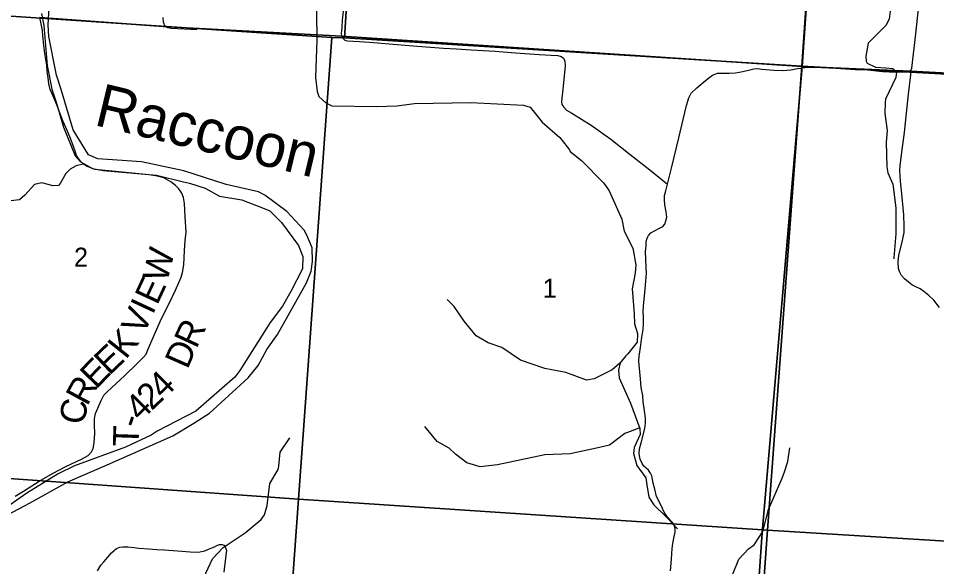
# Model space of a CAD drawing. Extents: x 1878108 to 2183446, y 146837 to 508383.
# Drawn here: x 2005354 to 2016069, y 304666 to 311060 of the extents above; entities that cross this region are included whole.
import ezdxf

# ---------------------------------------------------------------- set-up
doc = ezdxf.new("R2010")
doc.units = 0
for name, color, linetype in [('GM_X_Major_River', 7, 'Continuous'), ('GM_X_Major_River_Text', 7, 'Continuous'), ('GM_X_Minor_River', 7, 'Continuous'), ('GM_X_Section', 7, 'Continuous'), ('GM_X_Section_Text', 7, 'Continuous'), ('GM_X_Township', 7, 'Continuous'), ('GM_X_Township_Road', 7, 'Continuous'), ('GM_X_Township_Road_Text', 7, 'Continuous')]:
    doc.layers.add(name, color=color, linetype=linetype)

msp = doc.modelspace()

# ---------------------------------------------------------------- linework, layer by layer
at = {"layer": 'GM_X_Major_River'}
for points in [[(2005228, 305270), (2005424, 305377), (2005486, 305406), (2005933, 305654), (2006389, 305852), (2007158, 306191), (2007403, 306340), (2007585, 306455), (2008036, 306866), (2008152, 307010), (2008253, 307199), (2008377, 307372), (2008717, 307976), (2008771, 308113), (2008788, 308223), (2008782, 308383), (2008721, 308531), (2008687, 308589), (2008487, 308809), (2008230, 308998), (2008156, 309038), (2007778, 309121), (2007285, 309283), (2006791, 309386), (2006283, 309420), (2006174, 309468), (2005992, 309760), (2005852, 310230), (2005798, 310396), (2005710, 310847), (2005702, 310983), (2005715, 311185)], [(2005624, 311117), (2005650, 310977), (2005691, 310510), (2005744, 310234), (2005795, 310084), (2005879, 309791), (2006018, 309457), (2006081, 309387), (2006221, 309308), (2006343, 309284), (2006967, 309230), (2007281, 309155), (2007351, 309137), (2007534, 309078), (2007702, 308986), (2007960, 308943), (2008222, 308844), (2008288, 308816), (2008425, 308680), (2008624, 308413), (2008674, 308281), (2008670, 308140), (2008535, 307873), (2008438, 307705), (2008292, 307512), (2007940, 306953), (2007878, 306877), (2007423, 306481), (2006972, 306247), (2006904, 306200), (2006604, 306061), (2006009, 305842), (2005819, 305748), (2005452, 305524), (2005154, 305314)]]:
    msp.add_lwpolyline(points, dxfattribs=at)
at = {"layer": 'GM_X_Minor_River'}
for points in [[(2008830, 311302), (2008838, 310858), (2008838, 310810), (2008820, 310370), (2008840, 310206), (2008860, 310148), (2008940, 310073), (2009012, 310039), (2009536, 310034), (2009772, 310040), (2009978, 310067), (2010635, 310079), (2011247, 310048), (2011327, 310026), (2011467, 309849), (2011672, 309671), (2011758, 309562), (2011786, 309528), (2011794, 309506), (2011924, 309404), (2012186, 309137), (2012246, 309049), (2012394, 308718), (2012424, 308579), (2012524, 308381), (2012558, 308186), (2012550, 308090), (2012518, 307907), (2012539, 307614), (2012543, 307497), (2012579, 307385), (2012573, 307283), (2012467, 307146), (2012443, 307126), (2012375, 307044), (2012357, 306959), (2012365, 306869), (2012495, 306572), (2012607, 306277), (2012609, 306207), (2012541, 306054), (2012533, 305984), (2012569, 305845), (2012677, 305701), (2012687, 305620), (2012711, 305478), (2012767, 305388), (2012909, 305251), (2012937, 305223), (2013045, 305107)], [(2015535, 311207), (2015513, 311052), (2015477, 310978), (2015271, 310771), (2015241, 310618), (2015245, 310560), (2015259, 310536), (2015355, 310490), (2015477, 310482), (2015559, 310476), (2015599, 310434), (2015591, 310370), (2015471, 310118), (2015467, 310084), (2015464, 309952), (2015492, 309751), (2015480, 309615), (2015488, 309327), (2015500, 309259), (2015558, 309127), (2015592, 308852), (2015594, 308547), (2015568, 308268), (2015569, 308254)], [(2006124, 309363), (2006027, 309342), (2005957, 309301), (2005907, 309251), (2005843, 309133), (2005821, 309109), (2005759, 309106), (2005627, 309142), (2005541, 309122), (2005429, 308998), (2005368, 308945), (2005266, 308931), (2005092, 309003), (2005040, 308991), (2005018, 309003), (2004990, 309023), (2004894, 309098), (2004790, 309120), (2004596, 309200), (2004314, 309298), (2004220, 309346), (2004198, 309496), (2004124, 309591)], [(2012374, 307038), (2012283, 306963), (2012071, 306856), (2011985, 306842), (2011741, 306930), (2011498, 306978), (2011214, 307074), (2010994, 307223), (2010834, 307277), (2010696, 307359), (2010556, 307529), (2010440, 307698), (2010358, 307780)], [(2012604, 306285), (2012429, 306220), (2012251, 306082), (2012099, 306049), (2011794, 305983), (2011498, 305970), (2010946, 305853), (2010743, 305831), (2010587, 305877), (2010455, 305979), (2010379, 306046), (2010241, 306126), (2010095, 306300)], [(2006783, 303933), (2007000, 303932), (2007116, 303900), (2007250, 303934), (2007392, 304049), (2007470, 304145), (2007524, 304322), (2007527, 304394), (2007523, 304457), (2007543, 304589), (2007621, 304758), (2007745, 304890), (2008001, 305059), (2008189, 305214), (2008225, 305270), (2008257, 305379), (2008290, 305636), (2008384, 305799), (2008394, 305837), (2008408, 306001), (2008522, 306170)], [(2015152, 303640), (2015098, 303674), (2014911, 303777), (2014615, 303987), (2014496, 304053), (2014178, 304152), (2013904, 304166), (2013850, 304182), (2013729, 304311), (2013691, 304456), (2013687, 304570), (2013760, 304754), (2013872, 304874), (2013940, 304922), (2014039, 305077), (2014107, 305333), (2014266, 305696), (2014293, 305772), (2014331, 305892), (2014356, 306052)]]:
    msp.add_lwpolyline(points, dxfattribs=at)
at = {"layer": 'GM_X_Section'}
for points in [[(2004181, 316598), (2009499, 316192), (2009160, 310834), (2009010, 310838), (2003743, 311188)], [(2009499, 316192), (2014863, 315795), (2014496, 310501), (2009160, 310834)], [(2014863, 315795), (2020171, 315488), (2019788, 310210), (2014496, 310501)], [(2003529, 311206), (2003743, 311188), (2009010, 310838), (2008621, 305452), (2003175, 305842)], [(2009010, 310838), (2009160, 310834), (2014496, 310501), (2014095, 305091), (2008621, 305452)], [(2014496, 310501), (2019788, 310210), (2019399, 304766), (2014095, 305091)], [(2008621, 305452), (2008239, 300132), (2002740, 300503), (2003175, 305842)], [(2014095, 305091), (2013713, 299765), (2008239, 300132), (2008621, 305452)], [(2014095, 305091), (2019399, 304766), (2019035, 299380), (2013711, 299725), (2013713, 299765)]]:
    msp.add_lwpolyline(points, close=True, dxfattribs=at)
at = {"layer": 'GM_X_Township'}
for points in [[(2047300, 315672), (2046896, 308713), (2044671, 308870), (2043687, 308921), (2041417, 309015), (2041247, 309014), (2037098, 309204), (2031112, 309548), (2029101, 309655), (2027751, 309726), (2027032, 309764), (2024940, 309906), (2023383, 310046), (2023252, 310040), (2022929, 310063), (2022792, 310066), (2015762, 310446), (2014499, 310497), (2014658, 312772)], [(2014658, 312772), (2014499, 310497), (2009126, 310852), (2007464, 310941), (2007099, 310961), (2005605, 311070)], [(2005605, 311070), (2007099, 310961), (2007464, 310941), (2009126, 310852), (2014499, 310497), (2014033, 305062), (2013952, 303891), (2013758, 301109), (2013695, 300200), (2013680, 299994), (2013409, 296082), (2013072, 291229), (2012800, 287595), (2012779, 287296), (2012659, 285561), (2012605, 284781), (2012547, 283991), (2012147, 278506), (2012135, 278344), (2010382, 278455), (2009628, 278502), (2004300, 278840)], [(2012659, 285561), (2012779, 287296), (2012800, 287595), (2013072, 291229), (2013409, 296082), (2013680, 299994), (2013695, 300200), (2013758, 301109), (2013952, 303891), (2014033, 305062), (2014499, 310497), (2015762, 310446), (2022792, 310066), (2022929, 310063), (2023252, 310040), (2023383, 310046), (2024940, 309906), (2027032, 309764)]]:
    msp.add_lwpolyline(points, dxfattribs=at)
at = {"layer": 'GM_X_Township_Road'}
for points in [[(2015762, 310446), (2015780, 310481), (2015826, 310879), (2015870, 311283), (2015910, 311621), (2015935, 311858), (2015982, 312230)], [(2009150, 311210), (2009134, 311038), (2009129, 310960), (2009124, 310907)], [(2005315, 305486), (2005414, 305548), (2005596, 305661), (2005752, 305751), (2005908, 305835), (2006089, 305918), (2006170, 305964), (2006208, 306004), (2006228, 306045), (2006238, 306110), (2006246, 306221), (2006241, 306315), (2006243, 306389), (2006253, 306453), (2006280, 306516), (2006322, 306604), (2006353, 306666), (2006391, 306704), (2006597, 306895), (2006745, 307038), (2006815, 307108), (2006844, 307145), (2006865, 307196), (2006901, 307277), (2006954, 307399), (2007026, 307559), (2007112, 307734), (2007189, 307891), (2007254, 308042), (2007271, 308098), (2007283, 308184), (2007293, 308351), (2007300, 308469), (2007311, 308566), (2007300, 308745), (2007292, 308902), (2007281, 308970), (2007260, 309022), (2007227, 309070), (2007188, 309111), (2007135, 309154), (2007053, 309199), (2006979, 309220), (2006875, 309234), (2006645, 309260), (2006448, 309279), (2006248, 309298), (2006199, 309315), (2006157, 309334), (2006124, 309353), (2006089, 309384), (2006064, 309414), (2006034, 309461), (2006016, 309510), (2005969, 309640), (2005926, 309745), (2005874, 309866), (2005802, 310053), (2005761, 310151), (2005727, 310232), (2005710, 310296), (2005700, 310367), (2005690, 310442), (2005686, 310511), (2005664, 310650), (2005650, 310749), (2005640, 310855), (2005634, 310920), (2005619, 310995), (2005603, 311070)], [(2007054, 310997), (2007049, 311015), (2007045, 311070)], [(2007438, 310928), (2007137, 310941), (2007100, 310948), (2007075, 310962), (2007059, 310982), (2007054, 310997)], [(2009124, 310907), (2009122, 310891), (2009126, 310852), (2009139, 310827), (2009163, 310806), (2009194, 310797), (2009334, 310790), (2009452, 310783), (2009728, 310760), (2009959, 310740), (2010316, 310712), (2010466, 310703), (2010637, 310694), (2010919, 310679), (2011153, 310658), (2011429, 310640), (2011571, 310632), (2011647, 310628), (2011688, 310617), (2011713, 310595), (2011730, 310562), (2011733, 310505), (2011709, 310232), (2011697, 310131), (2011693, 310088), (2011697, 310057), (2011717, 310023), (2011749, 309990), (2011813, 309956), (2012036, 309816), (2012268, 309652), (2012494, 309472), (2012722, 309292), (2012929, 309126)], [(2012965, 304617), (2012974, 304754), (2012981, 304877), (2012989, 304936), (2013008, 305017), (2013019, 305070), (2013018, 305113), (2013005, 305150), (2012986, 305179), (2012929, 305244), (2012890, 305301), (2012851, 305385), (2012801, 305484), (2012779, 305568), (2012762, 305640), (2012744, 305727), (2012731, 305758), (2012706, 305790), (2012652, 305838), (2012633, 305867), (2012611, 305920), (2012599, 305983), (2012602, 306040), (2012620, 306110), (2012664, 306278), (2012671, 306340), (2012672, 306398), (2012659, 306482), (2012646, 306589), (2012639, 306660), (2012623, 306757), (2012614, 306856), (2012596, 307019), (2012592, 307066), (2012599, 307122), (2012612, 307220), (2012626, 307316), (2012644, 307433), (2012647, 307503), (2012647, 307578), (2012643, 307637), (2012649, 307707), (2012659, 307822), (2012672, 307947), (2012683, 308089), (2012679, 308153), (2012674, 308252), (2012673, 308343), (2012678, 308408), (2012681, 308459), (2012691, 308498), (2012708, 308529), (2012732, 308560), (2012775, 308584), (2012835, 308612), (2012872, 308634), (2012896, 308659), (2012910, 308698), (2012920, 308743), (2012911, 308805), (2012899, 308887), (2012893, 308943), (2012895, 308993), (2012909, 309050), (2012929, 309126), (2012974, 309314), (2013059, 309666), (2013112, 309880), (2013151, 310045), (2013177, 310133), (2013205, 310187), (2013269, 310249), (2013391, 310352), (2013455, 310397), (2013512, 310419), (2013557, 310422), (2013646, 310421), (2013720, 310423), (2013806, 310441), (2013890, 310460), (2013936, 310472), (2013981, 310474), (2014028, 310468), (2014169, 310457), (2014276, 310450), (2014367, 310460), (2014446, 310474)], [(2014446, 310474), (2014487, 310481), (2014498, 310482), (2014572, 310491), (2014726, 310487), (2014892, 310481), (2015119, 310464), (2015264, 310459), (2015437, 310442), (2015592, 310431), (2015705, 310436), (2015762, 310446)], [(2016103, 307690), (2016036, 307773), (2015979, 307829), (2015918, 307876), (2015878, 307904), (2015824, 307931), (2015781, 307953), (2015740, 307982), (2015695, 308022), (2015659, 308063), (2015634, 308106), (2015625, 308143), (2015621, 308217), (2015629, 308297), (2015662, 308434), (2015689, 308561), (2015688, 308638), (2015684, 308769), (2015678, 308852), (2015665, 308974), (2015648, 309162), (2015639, 309284), (2015643, 309341), (2015663, 309501), (2015694, 309730), (2015716, 309956), (2015740, 310175), (2015769, 310402), (2015762, 310446)], [(2006278, 304617), (2006316, 304683), (2006350, 304724), (2006400, 304778), (2006440, 304828), (2006473, 304856), (2006500, 304876), (2006538, 304892), (2006572, 304899), (2006632, 304899), (2006707, 304889), (2006759, 304883), (2006871, 304875), (2006970, 304866), (2007058, 304861), (2007161, 304854), (2007260, 304846), (2007360, 304838), (2007455, 304835), (2007491, 304841), (2007529, 304849), (2007571, 304868), (2007612, 304884), (2007642, 304897), (2007670, 304912), (2007700, 304926), (2007733, 304926), (2007752, 304915), (2007769, 304898), (2007776, 304876), (2007781, 304853), (2007776, 304798), (2007769, 304730), (2007758, 304671), (2007750, 304603)]]:
    msp.add_lwpolyline(points, dxfattribs=at)

# ---------------------------------------------------------------- texts
at = {"layer": 'GM_X_Major_River_Text'}
msp.add_text('Raccoon', height=500, rotation=346.5106, dxfattribs=at).set_placement((2006224, 309819))
at = {"layer": 'GM_X_Section_Text'}
for s, p in [('2', (2006003, 308165)), ('1', (2011472, 307803))]:
    msp.add_text(s, height=221, rotation=0, dxfattribs=at).set_placement(p)
at = {"layer": 'GM_X_Township_Road_Text'}
for s, rotation, p in [('W', 76.2868, (2007090, 307970)), ('E', 65.1257, (2006974, 307706)), ('I', 64.9433, (2006922, 307594)), ('V', 66.4314, (2006817, 307354)), ('R', 65.261, (2007432, 307198)), ('K', 51.2922, (2006607, 307074)), ('D', 66.2348, (2007327, 306958)), ('E', 43.6423, (2006415, 306887)), ('E', 45.841, (2006261, 306728)), ('R', 61.6037, (2006157, 306529)), ('4', 44.1704, (2007046, 306608)), ('2', 43.561, (2006909, 306478)), ('4', 44.8675, (2006780, 306349)), ('C', 79.7016, (2006121, 306310)), ('-', 70.9615, (2006759, 306263)), ('T', 88.1632, (2006756, 306062))]:
    msp.add_text(s, height=300, rotation=rotation, dxfattribs=at).set_placement(p)

doc.saveas('drawing.dxf')
